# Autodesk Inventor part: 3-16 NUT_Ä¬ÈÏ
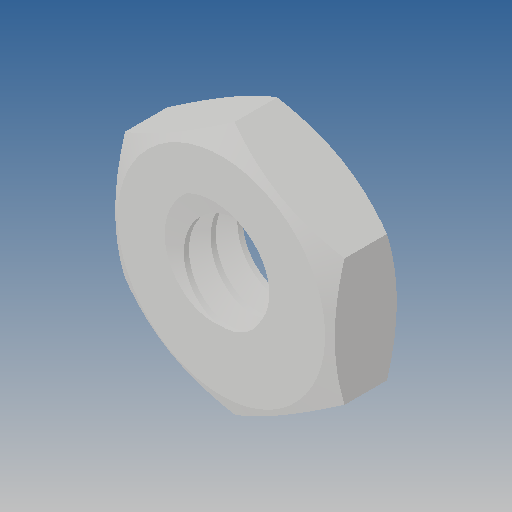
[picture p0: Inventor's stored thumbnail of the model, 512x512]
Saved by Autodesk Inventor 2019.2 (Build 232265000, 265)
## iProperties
Created: 2010-06
Part Number: 3-16 NUT_Ä¬ÈÏ
Material: Ogólny
Document SubType Name: Modeling
Designer: CADENGINEERING4
Density: 1 g/cm^3
Appearance: Domyślna
Author: CADENGINEERING4
Revision Number: ÈÎºÎ
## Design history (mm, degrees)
feature "NONE"
node "Bryła1"
